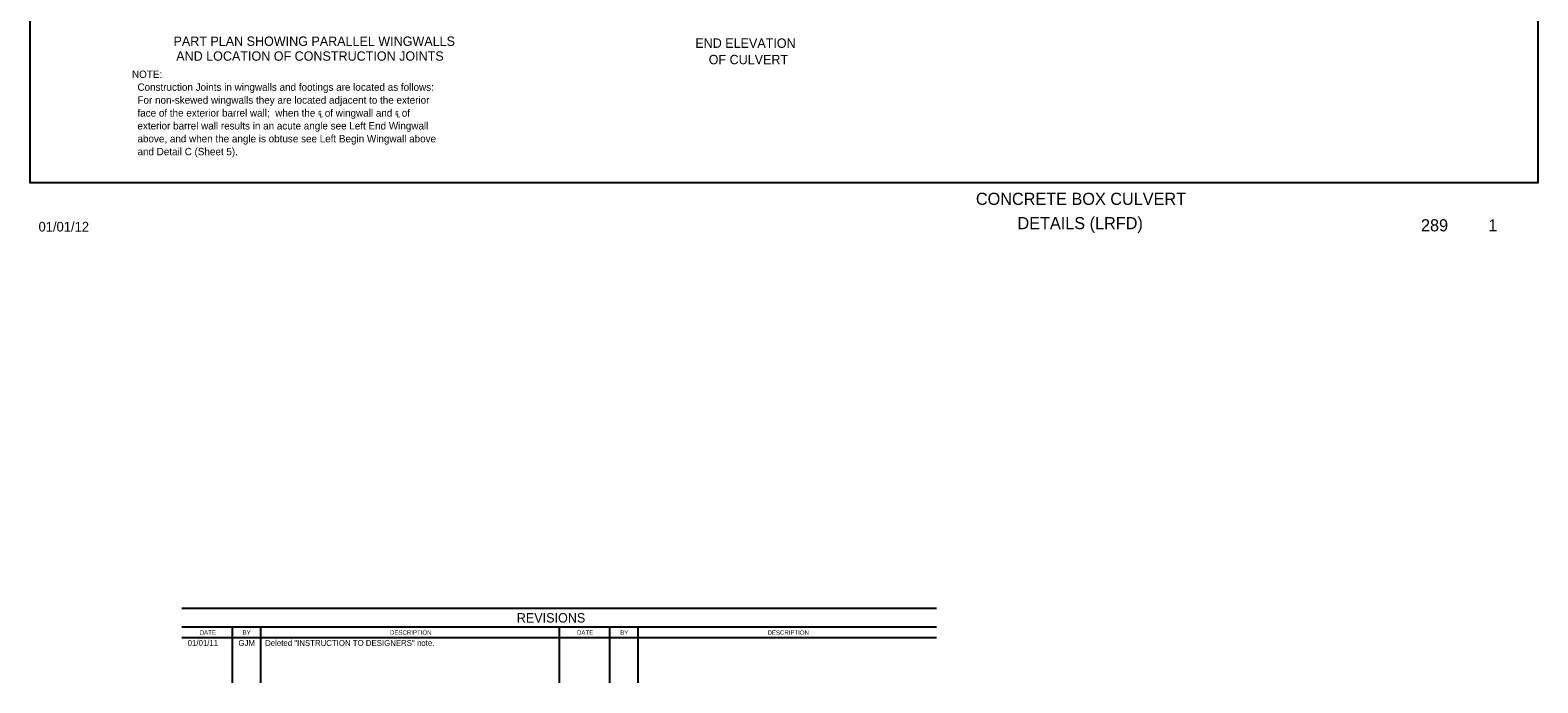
# Model space of a CAD drawing. Extents: x 6 to 291, y -45 to 111.
# Drawn here: x 5.5 to 159.9, y -44.5 to 22.3 of the extents above; entities that cross this region are included whole.
import ezdxf

# ---------------------------------------------------------------- set-up
doc = ezdxf.new("R2010")
doc.units = 0
for name, color, linetype in [('ActivePts-ConstElements', 7, 'Continuous'), ('AdhocPoint_dp', 7, 'Continuous'), ('DSDate', 7, 'Continuous'), ('DSIndex', 7, 'Continuous'), ('DSSheetNo', 7, 'Continuous'), ('DSTitle', 7, 'Continuous'), ('TextMisc', 7, 'Continuous')]:
    doc.layers.add(name, color=color, linetype=linetype)

msp = doc.modelspace()

# ---------------------------------------------------------------- linework, layer by layer
at = {"layer": 'ActivePts-ConstElements'}
msp.add_lwpolyline([(5.51, 105.09), (159.89, 105.09), (159.89, 6.65), (5.51, 6.65)], close=True, dxfattribs=at)
at = {"layer": 'TextMisc'}
for p, q in [((98.33, -36.92), (21.03, -36.92)), ((98.33, -38.85), (21.03, -38.85)), ((21.03, -39.88), (98.33, -39.88)), ((26.2, -38.85), (26.2, -44.53)), ((29.1, -38.85), (29.1, -44.53)), ((59.68, -38.85), (59.68, -44.53)), ((64.84, -38.85), (64.84, -44.53)), ((67.75, -38.85), (67.75, -44.53))]:
    msp.add_line(p, q, dxfattribs=at)

# ---------------------------------------------------------------- texts
at = {"layer": 'AdhocPoint_dp'}
for s, height, p in [('PART PLAN SHOWING PARALLEL WINGWALLS', 0.96, (20.19, 20.68)), ('AND LOCATION OF CONSTRUCTION JOINTS', 0.96, (20.47, 19.16)), ('END ELEVATION', 0.96, (73.62, 20.48)), ('OF CULVERT', 0.96, (74.99, 18.8)), ('NOTE:', 0.756, (15.94, 17.4)), ('  Construction Joints in wingwalls and footings are located as follows:', 0.756, (15.94, 16.08)), ('  For non-skewed wingwalls they are located adjacent to the exterior', 0.756, (15.94, 14.76)), ('  face of the exterior barrel wall;  when the ℄ of wingwall and ℄ of', 0.756, (15.94, 13.44)), ('  exterior barrel wall results in an acute angle see Left End Wingwall', 0.756, (15.94, 12.12)), ('  above, and when the angle is obtuse see Left Begin Wingwall above', 0.756, (15.94, 10.8)), ('  and Detail C (Sheet 5).', 0.756, (15.94, 9.48)), ('REVISIONS', 0.963, (55.34, -38.36)), ('01/01/11', 0.6, (21.64, -40.75)), ('BY', 0.45, (27.27, -39.61)), ('Deleted "INSTRUCTION TO DESIGNERS" note.', 0.6, (29.57, -40.75)), ('BY', 0.45, (65.92, -39.61)), ('GJM', 0.6, (26.84, -40.75))]:
    msp.add_text(s, height=height, dxfattribs=at).set_placement(p)
for s, height, rotation, p in [('DATE', 0.448, 359.8693, (22.87, -39.61)), ('DESCRIPTION', 0.4503, 0.0498, (42.36, -39.61)), ('DATE', 0.448, 359.8693, (61.51, -39.61)), ('DESCRIPTION', 0.4503, 0.0498, (81.01, -39.61))]:
    msp.add_text(s, height=height, rotation=rotation, dxfattribs=at).set_placement(p)
at = {"layer": 'DSDate'}
msp.add_text('01/01/12', height=0.994, dxfattribs=at).set_placement((6.37, 1.67))
at = {"layer": 'DSIndex'}
msp.add_text(' 289 ', height=1.243, dxfattribs=at).set_placement((147.46, 1.69))
at = {"layer": 'DSSheetNo'}
msp.add_text('  1   ', height=1.243, dxfattribs=at).set_placement((153.89, 1.69))
at = {"layer": 'DSTitle'}
for s, p in [('           CONCRETE BOX CULVERT           ', (97.27, 4.4)), ('              DETAILS (LRFD)                ', (100.14, 1.91))]:
    msp.add_text(s, height=1.2429, dxfattribs=at).set_placement(p)

doc.saveas('drawing.dxf')
